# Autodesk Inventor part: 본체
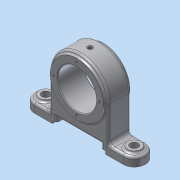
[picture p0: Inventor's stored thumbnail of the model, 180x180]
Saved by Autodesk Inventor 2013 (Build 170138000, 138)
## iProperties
Created: 2019-05
Part Number: 본체
Material: 알루미늄 6061
Document SubType Name: Modeling
Designer: dgall
Mass: 456.156 g
Surface Area: 319.371 cm^2
Volume: 168.323 cm^3
Density: 2.71 g/cm^3
Author: dgall
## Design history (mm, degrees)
sketch "스케치1"
  geometry: L1 (0, 0)-(150, 0); L2 (150, 0)-(150, 30); L3 (150, 30)-(0, 30); L4 (0, 30)-(0, 0)
  constraints: 8 end point, 2 parallel, 1 horizontal, 1 perpendicular
  dimensions: "d0" = 150 distance of L1.start L1.end; "d1" = 30 distance of L1.end L2.end
extrude "돌출1" new body sketch "스케치1" distance "d2" = 12; taper "d3" = 0 deg
node "작업 평면1"
sketch "스케치2"
  geometry: L1 (0, 0)-(150, 0) reference; L2 (0, 12)-(150, 12) reference; C1 r 40 at (75, 60); 1 further point
  constraints: 1 centre point, 1 midpoint, 1 vertical alignment
  dimensions: "d5" = 60 distance from line of L1 C1.centre; "d6" = 80 diameter of C1
extrude "돌출2" join sketch "스케치2" stored distance "d7" = 30; taper "d8" = 0 deg
sketch "스케치3"
  geometry: L1 (0, 0)-(150, 0) reference; L2 (150, 0)-(150, 12) reference; L3 (0, 12)-(150, 12) reference; L4 (0, 0)-(0, 12) reference; L5 (35, 60)-(35, 12); L6 (115, 60)-(115, 12); A1 r 40 centre (75, 60) between (35, 60) and (115, 60) reference; 1 further point
  constraints: 4 end point, 2 perpendicular, 2 point on circle, 2 point on line, 2 tangent
extrude "돌출3" join sketch "스케치3" stored distance "d9" = 30; taper "d10" = 0 deg
sketch "스케치4"
  geometry: L1 (0, 0)-(150, 0) reference; L2 (0, 0)-(0, 12) reference; L3 (39, 0)-(39, 4); L4 (39, 4)-(45, 4); L5 (45, 4)-(45, 10); L6 (45, 10)-(105, 10); L7 (105, 10)-(105, 4); L8 (105, 4)-(111, 4); L9 (111, 4)-(111, 0); 2 further points
  constraints: 14 end point, 5 parallel, 2 midpoint, 2 perpendicular, 2 point on line, 1 collinear, 1 vertical alignment
  dimensions: "d11" = 72 distance between parallel lines of L9 L3; "d13" = 60 distance between parallel lines of L7 L5; "d14" = 39 distance between parallel lines of L2 L3; "d15" = 10 distance between parallel lines of L1 L6; "d16" = 4 distance of L3.start L3.end
extrude "돌출4" cut sketch "스케치4" distance "d17" = 30; taper "d18" = 0 deg
fillet "모깎기1" dims "d28" = 15
sketch "스케치6"
  geometry: C1 r 9 at (15, 15); A1 r 15 centre (15, 15) between (15, 30) and (15, 0) reference; 1 further point
  constraints: 1 centre point, 1 coincident
  dimensions: "d29" = 18 diameter of C1
extrude "돌출5" join sketch "스케치6" distance "d31" = 3; taper "d32" = 0 deg
node "작업 평면2"
hole "구멍2" diameter "d36" = 11; stored, may be unused: countersink angle "d40" = 90 deg, drill point angle "d42" = 118 deg; dims "d34" = 10, "d35" = 10, "d37" = 6, "d38" = 4, "d39" = 2, "d41" = 8
hole "구멍3" diameter "d45" = 11; stored, may be unused: countersink angle "d49" = 90 deg, drill point angle "d51" = 118 deg; dims "d43" = 10, "d44" = 10, "d46" = 6, "d47" = 4, "d48" = 2, "d50" = 8
sketch "스케치8"
  geometry: C1 r 36 at (0, 0); A1 r 40 centre (0, 0) between (40, 0) and (-40, 0) reference; 1 further point
  constraints: 1 centre point, 1 coincident
  dimensions: "d63" = 72 diameter of C1
extrude "돌출7" join sketch "스케치8" distance "d67" = 3; taper "d68" = 0 deg
node "작업 평면3"
hole "구멍5" diameter "d71" = 52; stored, may be unused: countersink angle "d75" = 90 deg, drill point angle "d77" = 118 deg; dims "d72" = 6, "d73" = 4, "d74" = 2, "d76" = 8, "d87" = 10, "d88" = 10
sketch "스케치9" dims "d89" = 62
  geometry: L1 (0, 0)-(0, 31); C1 r 26 at (0, 0) reference; C2 r 36 at (0, 0) reference; 1 further point
  constraints: 2 end point, 1 coincident, 1 vertical, 1 vertical alignment, 2 other
node "작업점2"
hole "구멍7" diameter "d93" = 3.242; stored, may be unused: countersink angle "d97" = 90 deg, drill point angle "d99" = 118 deg; dims "d91" = 10, "d92" = 10, "d94" = 6, "d95" = 4, "d96" = 2, "d98" = 8
sketch "스케치10"
  geometry: L1 (0, 0)-(0, 26); C1 r 36 at (0, 0) reference; C2 r 1.5 at (0, 26); 2 further points
  constraints: 2 end point, 1 centre point, 1 coincident, 1 vertical, 1 vertical alignment, 1 other
  dimensions: "d103" = 3 diameter of C2
extrude "돌출8" cut sketch "스케치10" distance "d105" = 36; taper "d106" = 0 deg
node "작업 평면5"
sketch "스케치12"
  geometry: L1 (0, 0)-(-75, 0); L2 (-35, 30)-(-35, 0) reference; L3 (-115, 0)-(-35, 0) reference; L4 (-115, 30)-(-115, 0) reference; L5 (-35, 30)-(-115, 30) reference; L6 (-35, 15)-(-115, 15); L7 (-75, 0)-(-75, 15)
  constraints: 6 end point, 3 midpoint, 1 horizontal
  dimensions: "d108" = 75 distance of L1.start L1.end
  node "투영된 루프3"
node "작업점3"
hole "구멍8" sketch "스케치12" diameter "d109" = 4.917; stored, may be unused: countersink angle "d113" = 90 deg, drill point angle "d115" = 118 deg; dims "d110" = 7, "d111" = 7, "d112" = 1, "d114" = 9
chamfer "모따기1" distance "d116" = 1; stored, may be unused: second distance "d117" = 2, angle "d118" = 45 deg
fillet "모깎기2" dims "d119" = 3
fillet "모깎기3" dims "d120" = 3
fillet "모깎기4" dims "d121" = 3
fillet "모깎기5" dims "d122" = 3
fillet "모깎기6" dims "d123" = 6
sketch "스케치13"
  geometry: L1 (66, -6)-(6, -6) reference; A1 r 39 centre (36, -56) between (73, -43.671) and (-1, -43.671) reference; 2 further points
  constraints: 1 vertical alignment, 1 other
  dimensions: "d124" = 7 distance from line of point (36, -13) L1
feature "엠보싱1" sketch "스케치13" dims "d125" = 0.5, "d126" = 0
sketch "스케치14"
  geometry: L1 (-35, 27)-(-115, 27) reference; L2 (-35, 27)-(-35, 3) reference; L3 (-115, 3)-(-35, 3) reference; L4 (-115, 27)-(-115, 3) reference; C1 r 3.5 at (-75, 15) reference; C2 r 2.458 at (-75, 15) reference; C3 r 1 at (-75, 15); 3 further points
  constraints: 2 vertical alignment, 1 centre point, 1 coincident
  dimensions: "d127" = 2 diameter of C3
extrude "돌출9" cut sketch "스케치14" stored distance "d129" = 10; taper "d130" = 0 deg
node "솔리드1"
mirror "대칭1"
mirror "대칭2"
pattern_circular "원형 패턴1" dims angle "d101" = 360 deg
mirror "대칭3"
node "투영된 루프1"
node "투영된 루프2"
node "작업 평면4"
node "투영된 루프4"
node "투영된 루프5"
other parameters: "d4" = -15, "d33" = 75
